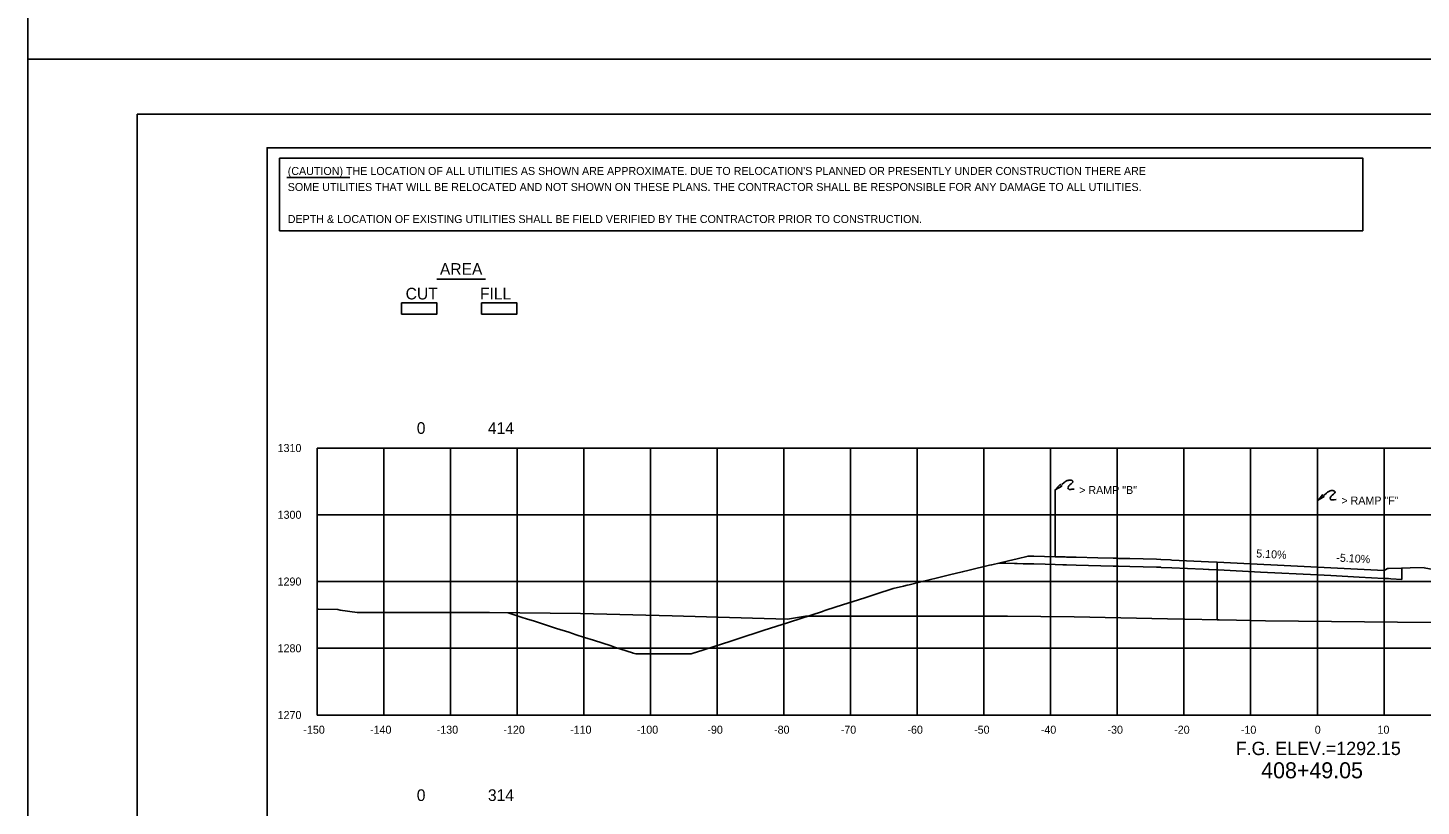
# Model space of a CAD drawing. Extents: x 2148105 to 2149976, y 144169 to 149705.
# Drawn here: x 2148219.9 to 2148428.9, y 144793.3 to 144909.9 of the extents above; entities that cross this region are included whole.
import ezdxf

# ---------------------------------------------------------------- set-up
doc = ezdxf.new("R2010")
doc.units = 0
for name, color, linetype in [('Bridge M-Header', 7, 'Continuous'), ('Default', 7, 'Continuous'), ('EX_Align', 7, 'Continuous'), ('INR_Tracking', 7, 'Continuous'), ('PH1a-PR-ServRd', 7, 'Continuous'), ('PH2-PR-Barrier', 7, 'Continuous'), ('PR-Dividing Strip', 7, 'Continuous'), ('PR_Align_PC', 7, 'Continuous'), ('PR_Align_PI', 7, 'Continuous'), ('PR_Align_Ramp_E', 7, 'Continuous'), ('PR_Align_Ramp_J', 7, 'Continuous'), ('PR_Storm_Channel', 7, 'Continuous'), ('PR_Storm_Conc_Box_PH1B', 7, 'Continuous'), ('PR_Storm_Conc_Pipe', 7, 'Continuous'), ('PR_Storm_Conc_Pipe_PH1B', 7, 'Continuous'), ('PR_Storm_Inlet_CICI_PH1B', 7, 'Continuous'), ('PR_Storm_Junction_Box_PH1B', 7, 'Continuous'), ('PR_Storm_MH', 7, 'Continuous'), ('PR_Storm_MH_PH1B', 7, 'Continuous'), ('PR_Storm_Standard_Median_Drain_PH1B', 7, 'Continuous'), ('TopCut', 7, 'Continuous'), ('TOPO_BRIDGE_Pier Cap', 7, 'Continuous')]:
    doc.layers.add(name, color=color, linetype=linetype)

# ---------------------------------------------------------------- blocks, each defined once
blk = doc.blocks.new('POINT_DISPLAY')
at = {"layer": 'Default'}
blk.add_line((0, 0), (0, 0), dxfattribs=at)

msp = doc.modelspace()

# ---------------------------------------------------------------- linework, layer by layer
at = {"layer": 'EX_Align'}
msp.add_lwpolyline([(2148291.95, 144822.22), (2148294.08, 144821.54), (2148294.71, 144821.33), (2148295.91, 144820.95), (2148296.22, 144820.85), (2148299.22, 144819.89), (2148301.06, 144819.3), (2148302.16, 144818.94), (2148303.43, 144818.53), (2148304.75, 144818.11), (2148307.4, 144817.26), (2148307.94, 144817.08), (2148310.64, 144816.22), (2148310.71, 144816.19), (2148311.13, 144816.06), (2148312.62, 144816.06), (2148313.74, 144816.06), (2148314.5, 144816.06), (2148315.26, 144816.06), (2148316.56, 144816.06), (2148317.85, 144816.06), (2148318.39, 144816.06), (2148319.4, 144816.07), (2148320.04, 144816.27), (2148320.08, 144816.29), (2148324.27, 144817.64), (2148325.05, 144817.89), (2148326.13, 144818.24), (2148326.43, 144818.33), (2148330.21, 144819.56), (2148332.26, 144820.22), (2148332.55, 144820.31), (2148332.77, 144820.38), (2148335.73, 144821.34), (2148339.11, 144822.43), (2148339.23, 144822.47), (2148339.47, 144822.55), (2148341.18, 144823.1), (2148345.45, 144824.48), (2148345.62, 144824.54), (2148346.67, 144824.88), (2148347.12, 144825.02), (2148349.69, 144825.85), (2148351.28, 144826.23), (2148351.79, 144826.36), (2148352.11, 144826.43), (2148353.88, 144826.86), (2148356.35, 144827.46), (2148358.14, 144827.89), (2148360.06, 144828.35), (2148361.09, 144828.6), (2148364.18, 144829.34), (2148364.48, 144829.41), (2148364.69, 144829.46), (2148365.57, 144829.68), (2148366.61, 144829.65), (2148367.92, 144829.62), (2148368.05, 144829.61), (2148368.3, 144829.61), (2148369.21, 144829.58), (2148369.95, 144829.56), (2148370.49, 144829.55), (2148370.82, 144829.54), (2148372.52, 144829.5), (2148374, 144829.46), (2148375.15, 144829.43), (2148375.5, 144829.42), (2148375.69, 144829.42), (2148377.16, 144829.38), (2148378.98, 144829.33), (2148382.71, 144829.23), (2148383.03, 144829.23), (2148383.51, 144829.21), (2148385.18, 144829.17), (2148389.19, 144829.07), (2148389.85, 144829.04), (2148389.85, 144829.04), (2148389.92, 144829.03), (2148391.49, 144828.96), (2148396.19, 144828.75), (2148396.99, 144828.71), (2148397.12, 144828.71), (2148398.32, 144828.65)], dxfattribs=at)
at = {"layer": 'INR_Tracking'}
msp.add_lwpolyline([(2148398.32, 144828.65), (2148398.43, 144828.65), (2148404.8, 144828.32), (2148413.32, 144827.89), (2148415.32, 144827.79), (2148419.6, 144827.57), (2148423.29, 144827.38), (2148423.32, 144827.38), (2148423.99, 144827.35), (2148423.99, 144827.35), (2148424.33, 144827.33), (2148425.97, 144827.24), (2148425.98, 144827.49), (2148425.98, 144827.58), (2148425.99, 144828.92), (2148426, 144828.92), (2148427.23, 144828.94), (2148429.32, 144828.99), (2148429.33, 144828.98), (2148441.47, 144826.69), (2148474.14, 144820.53)], dxfattribs=at)
at = {"layer": 'PH1a-PR-ServRd'}
msp.add_lwpolyline([(2148570.82, 144681.91), (2148255.82, 144681.91), (2148255.82, 144891.91), (2148570.82, 144891.91)], close=True, dxfattribs=at)
at = {"layer": 'PH2-PR-Barrier'}
msp.add_line((2148413.32, 144829.06), (2148413.32, 144839.06), dxfattribs=at)
for points in [[(2148413.32, 144839.06), (2148413.84, 144839.61), (2148414.1, 144839.91), (2148414.18, 144839.74), (2148414.32, 144839.63), (2148413.32, 144839.06)], [(2148414.33, 144839.87), (2148414.69, 144840.16), (2148414.85, 144840.29), (2148414.94, 144840.36), (2148415.04, 144840.42), (2148415.14, 144840.46), (2148415.26, 144840.5), (2148415.39, 144840.53), (2148415.49, 144840.54), (2148415.57, 144840.54), (2148415.65, 144840.53), (2148415.72, 144840.52), (2148415.78, 144840.51), (2148415.83, 144840.48), (2148415.87, 144840.46), (2148415.91, 144840.43), (2148415.95, 144840.38), (2148415.98, 144840.33), (2148415.97, 144840.27), (2148415.96, 144840.23), (2148415.91, 144840.16), (2148415.72, 144840), (2148415.53, 144839.83), (2148415.46, 144839.76), (2148415.39, 144839.68), (2148415.33, 144839.59), (2148415.29, 144839.53), (2148415.25, 144839.44), (2148415.25, 144839.36), (2148415.27, 144839.28), (2148415.31, 144839.21), (2148415.36, 144839.17), (2148415.42, 144839.15), (2148415.53, 144839.13), (2148415.66, 144839.14), (2148415.82, 144839.16), (2148416.15, 144839.19)]]:
    msp.add_lwpolyline(points, dxfattribs=at)
at = {"layer": 'PR-Dividing Strip'}
msp.add_line((2148374, 144830.63), (2148374, 144840.63), dxfattribs=at)
for points in [[(2148375.01, 144841.44), (2148375.36, 144841.73), (2148375.52, 144841.86), (2148375.62, 144841.93), (2148375.72, 144841.99), (2148375.82, 144842.03), (2148375.93, 144842.07), (2148376.07, 144842.1), (2148376.16, 144842.11), (2148376.25, 144842.11), (2148376.33, 144842.1), (2148376.4, 144842.09), (2148376.45, 144842.08), (2148376.51, 144842.06), (2148376.55, 144842.03), (2148376.59, 144842), (2148376.62, 144841.95), (2148376.65, 144841.9), (2148376.65, 144841.84), (2148376.64, 144841.8), (2148376.58, 144841.73), (2148376.4, 144841.57), (2148376.21, 144841.41), (2148376.13, 144841.33), (2148376.07, 144841.26), (2148376.01, 144841.16), (2148375.97, 144841.1), (2148375.93, 144841.01), (2148375.92, 144840.93), (2148375.95, 144840.85), (2148375.99, 144840.78), (2148376.04, 144840.75), (2148376.09, 144840.72), (2148376.2, 144840.71), (2148376.34, 144840.71), (2148376.49, 144840.73), (2148376.83, 144840.77)], [(2148374, 144840.63), (2148374.51, 144841.18), (2148374.78, 144841.48), (2148374.86, 144841.32), (2148375, 144841.2), (2148374, 144840.63)]]:
    msp.add_lwpolyline(points, dxfattribs=at)
at = {"layer": 'PR_Align_PC'}
msp.add_line((2148281.28, 144872.21), (2148288.56, 144872.21), dxfattribs=at)
for points in [[(2148275.98, 144868.66), (2148281.29, 144868.66), (2148281.29, 144866.97), (2148275.98, 144866.97)], [(2148275.98, 144868.66), (2148281.29, 144868.66), (2148281.29, 144866.97), (2148275.98, 144866.97)], [(2148287.98, 144868.66), (2148293.29, 144868.66), (2148293.29, 144866.97), (2148287.98, 144866.97)], [(2148287.98, 144868.66), (2148293.29, 144868.66), (2148293.29, 144866.97), (2148287.98, 144866.97)]]:
    msp.add_lwpolyline(points, close=True, dxfattribs=at)
at = {"layer": 'PR_Align_PI'}
msp.add_lwpolyline([(2148365.57, 144829.68), (2148367.03, 144830.03), (2148368.3, 144830.33), (2148369.95, 144830.73), (2148370.82, 144830.71), (2148374, 144830.63), (2148375.51, 144830.59), (2148375.69, 144830.58), (2148377.17, 144830.54), (2148380.38, 144830.46), (2148382.71, 144830.4), (2148383.19, 144830.39), (2148383.51, 144830.38), (2148385.18, 144830.34), (2148389.19, 144830.24), (2148389.85, 144830.2), (2148391.32, 144830.14), (2148391.49, 144830.13), (2148392.61, 144830.08), (2148396.99, 144829.88), (2148398.32, 144829.82)], dxfattribs=at)
at = {"layer": 'PR_Align_Ramp_E'}
for points in [[(2148219.95, 145145.16), (2148579.95, 145145.16), (2148579.95, 144905.16), (2148219.95, 144905.16)], [(2148219.95, 144905.16), (2148579.95, 144905.16), (2148579.95, 144665.16), (2148219.95, 144665.16)]]:
    msp.add_lwpolyline(points, close=True, dxfattribs=at)
at = {"layer": 'PR_Align_Ramp_J'}
msp.add_lwpolyline([(2148236.32, 144896.91), (2148576.32, 144896.91), (2148576.32, 144676.91), (2148236.32, 144676.91)], close=True, dxfattribs=at)
at = {"layer": 'PR_Storm_Channel'}
msp.add_lwpolyline([(2148398.32, 144829.82), (2148413.32, 144829.06), (2148415.32, 144828.95), (2148423.32, 144828.55), (2148423.82, 144828.88), (2148423.99, 144828.88), (2148425.99, 144828.92)], dxfattribs=at)
at = {"layer": 'PR_Storm_Conc_Box_PH1B'}
for p, q in [((2148263.32, 144846.91), (2148563.32, 144846.91)), ((2148263.32, 144806.91), (2148263.32, 144846.91)), ((2148273.32, 144806.91), (2148273.32, 144846.91)), ((2148283.32, 144806.91), (2148283.32, 144846.91)), ((2148293.32, 144806.91), (2148293.32, 144846.91)), ((2148303.32, 144806.91), (2148303.32, 144846.91)), ((2148313.32, 144806.91), (2148313.32, 144846.91)), ((2148323.32, 144806.91), (2148323.32, 144846.91)), ((2148333.32, 144806.91), (2148333.32, 144846.91)), ((2148343.32, 144806.91), (2148343.32, 144846.91)), ((2148353.32, 144806.91), (2148353.32, 144846.91)), ((2148363.32, 144806.91), (2148363.32, 144846.91)), ((2148373.32, 144806.91), (2148373.32, 144846.91)), ((2148383.32, 144806.91), (2148383.32, 144846.91)), ((2148393.32, 144806.91), (2148393.32, 144846.91)), ((2148403.32, 144806.91), (2148403.32, 144846.91)), ((2148413.32, 144806.91), (2148413.32, 144846.91)), ((2148423.32, 144806.91), (2148423.32, 144846.91)), ((2148263.32, 144836.91), (2148563.32, 144836.91)), ((2148263.32, 144826.91), (2148563.32, 144826.91)), ((2148263.32, 144816.91), (2148563.32, 144816.91)), ((2148263.32, 144806.91), (2148563.32, 144806.91))]:
    msp.add_line(p, q, dxfattribs=at)
at = {"layer": 'PR_Storm_Conc_Pipe'}
msp.add_lwpolyline([(2148398.32, 144828.65), (2148398.32, 144828.99), (2148398.32, 144829.82)], dxfattribs=at)
at = {"layer": 'PR_Storm_Conc_Pipe_PH1B'}
msp.add_lwpolyline([(2148255.82, 144681.91), (2148570.82, 144681.91), (2148570.82, 144891.91), (2148255.82, 144891.91)], close=True, dxfattribs=at)
msp.add_lwpolyline([(2148255.82, 144681.91), (2148570.82, 144681.91), (2148570.82, 144891.91), (2148255.82, 144891.91)], close=True, dxfattribs=at)
at = {"layer": 'PR_Storm_Inlet_CICI_PH1B'}
msp.add_lwpolyline([(2148263.32, 144822.76), (2148263.52, 144822.75), (2148266.41, 144822.73), (2148266.77, 144822.62), (2148269.35, 144822.29), (2148289.17, 144822.25), (2148302.82, 144822.11), (2148316.58, 144821.75), (2148328.6, 144821.42), (2148333.86, 144821.28), (2148335.98, 144821.64), (2148336.58, 144821.74), (2148353.95, 144821.74), (2148358.31, 144821.7), (2148366.87, 144821.72), (2148376.83, 144821.61), (2148390.86, 144821.3), (2148401.2, 144821.13), (2148405.54, 144821.04), (2148425.33, 144820.82), (2148431.4, 144820.76)], dxfattribs=at)
at = {"layer": 'PR_Storm_MH'}
msp.add_line((2148258.8, 144887.46), (2148268.21, 144887.46), dxfattribs=at)
msp.add_lwpolyline([(2148257.69, 144890.34), (2148420.12, 144890.34), (2148420.12, 144879.47), (2148257.69, 144879.47)], close=True, dxfattribs=at)
at = {"layer": 'PR_Storm_Standard_Median_Drain_PH1B'}
for q in [(2148263.32, 144846.91), (2148563.32, 144806.91)]:
    msp.add_line((2148263.32, 144806.91), q, dxfattribs=at)
at = {"layer": 'TopCut'}
for points in [[(2148287.98, 144866.97), (2148293.29, 144866.97), (2148293.29, 144868.66), (2148287.98, 144868.66), (2148287.98, 144866.97)], [(2148429.32, 144828.99), (2148427.23, 144828.94), (2148426, 144828.92), (2148425.99, 144828.92), (2148425.98, 144827.58), (2148425.98, 144827.49), (2148425.97, 144827.24), (2148424.33, 144827.33), (2148423.99, 144827.35), (2148423.99, 144827.35), (2148423.32, 144827.38), (2148423.29, 144827.38), (2148419.6, 144827.57), (2148415.32, 144827.79), (2148413.32, 144827.89), (2148404.8, 144828.32), (2148398.43, 144828.65), (2148398.32, 144828.65), (2148398.32, 144821.18), (2148401.2, 144821.13), (2148405.54, 144821.04), (2148425.33, 144820.82), (2148431.4, 144820.76)]]:
    msp.add_lwpolyline(points, dxfattribs=at)
at = {"layer": 'TOPO_BRIDGE_Pier Cap'}
msp.add_lwpolyline([(2148275.98, 144866.97), (2148281.29, 144866.97), (2148281.29, 144868.66), (2148275.98, 144868.66), (2148275.98, 144866.97)], dxfattribs=at)

# ---------------------------------------------------------------- block references
at = {"layer": 'PR_Storm_Conc_Pipe_PH1B', "xscale": 10, "yscale": 10}
for p in [(2148398.32, 144829.82), (2148398.32, 144829.82), (2148415.32, 144828.95), (2148415.32, 144828.95), (2148423.32, 144828.55), (2148423.32, 144828.55)]:
    msp.add_blockref('POINT_DISPLAY', p, dxfattribs=at)

# ---------------------------------------------------------------- texts
at = {"layer": 'Bridge M-Header'}
for s, p in [('5.10%', (2148404.13, 144830.53)), ('-5.10%', (2148416.14, 144829.91))]:
    msp.add_text(s, height=1.2, rotation=357.0804, dxfattribs=at).set_placement(p)
at = {"layer": 'PH2-PR-Barrier'}
msp.add_text('> RAMP "F"', height=1.2, rotation=360, dxfattribs=at).set_placement((2148416.92, 144838.45))
at = {"layer": 'PR-Dividing Strip'}
msp.add_text('> RAMP "B"', height=1.2, rotation=360, dxfattribs=at).set_placement((2148377.6, 144840.02))
at = {"layer": 'PR_Align_PC'}
for s, p in [('AREA', (2148281.74, 144872.86)), ('CUT', (2148276.6, 144869.17)), ('FILL', (2148287.74, 144869.17)), ('0', (2148278.27, 144849.03)), ('414', (2148288.94, 144849.03)), ('0', (2148278.27, 144794.03)), ('314', (2148288.94, 144794.03))]:
    msp.add_text(s, height=1.75, dxfattribs=at).set_placement(p)
at = {"layer": 'PR_Storm_Junction_Box_PH1B'}
msp.add_text('408+49.05', height=2.4, dxfattribs=at).set_placement((2148404.9, 144797.43))
at = {"layer": 'PR_Storm_MH'}
for s, p in [("(CAUTION) THE LOCATION OF ALL UTILITIES AS SHOWN ARE APPROXIMATE. DUE TO RELOCATION'S PLANNED OR PRESENTLY UNDER CONSTRUCTION THERE ARE ", (2148258.92, 144887.82)), ('SOME UTILITIES THAT WILL BE RELOCATED AND NOT SHOWN ON THESE PLANS. THE CONTRACTOR SHALL BE RESPONSIBLE FOR ANY DAMAGE TO ALL UTILITIES.', (2148258.92, 144885.42)), ('DEPTH & LOCATION OF EXISTING UTILITIES SHALL BE FIELD VERIFIED BY THE CONTRACTOR PRIOR TO CONSTRUCTION.', (2148258.92, 144880.62))]:
    msp.add_text(s, height=1.2, dxfattribs=at).set_placement(p)
at = {"layer": 'PR_Storm_MH_PH1B'}
for s, height, p in [('1310', 1.2, (2148257.4, 144846.31)), ('1300', 1.2, (2148257.4, 144836.31)), ('1290', 1.2, (2148257.4, 144826.31)), ('1280', 1.2, (2148257.4, 144816.31)), ('1270', 1.2, (2148257.4, 144806.31)), ('-150', 1.2, (2148261.26, 144804.11)), ('-140', 1.2, (2148271.26, 144804.11)), ('-130', 1.2, (2148281.26, 144804.11)), ('-120', 1.2, (2148291.26, 144804.11)), ('-110', 1.2, (2148301.26, 144804.11)), ('-100', 1.2, (2148311.26, 144804.11)), ('-90', 1.2, (2148321.85, 144804.11)), ('-80', 1.2, (2148331.85, 144804.11)), ('-70', 1.2, (2148341.85, 144804.11)), ('-60', 1.2, (2148351.85, 144804.11)), ('-50', 1.2, (2148361.85, 144804.11)), ('-40', 1.2, (2148371.85, 144804.11)), ('-30', 1.2, (2148381.85, 144804.11)), ('-20', 1.2, (2148391.85, 144804.11)), ('-10', 1.2, (2148401.85, 144804.11)), ('0', 1.2, (2148412.93, 144804.11)), ('10', 1.2, (2148422.34, 144804.11)), ('F.G. ELEV.=1292.15', 2, (2148401.08, 144800.91))]:
    msp.add_text(s, height=height, dxfattribs=at).set_placement(p)

doc.saveas('drawing.dxf')
